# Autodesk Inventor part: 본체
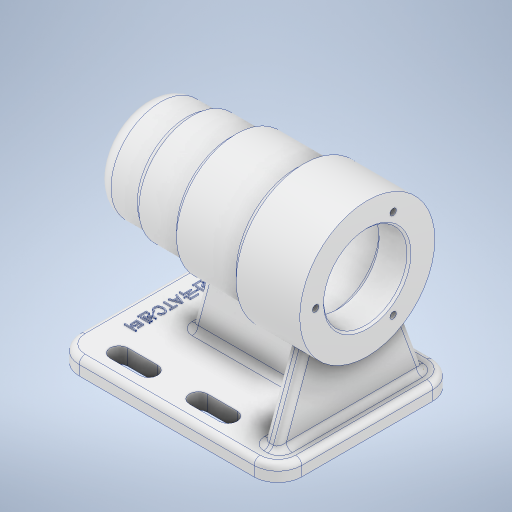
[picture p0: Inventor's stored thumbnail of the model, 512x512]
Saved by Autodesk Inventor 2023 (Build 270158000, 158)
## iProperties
Created: 2022-07
Part Number: 본체
Material: 알루미늄 6061
Document SubType Name: Modeling
Designer: owner
Density: 2.7 g/cm^3
Appearance: 알루미늄 - 평지
Mass: 694.882 g
Surface Area: 704.892 cm^2
Volume: 257.364 cm^3
Author: owner
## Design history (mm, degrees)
sketch "스케치1"
  geometry: L1 (56, -45)-(-56, -45); L2 (-56, -45)-(-56, 45); L3 (-56, 45)-(56, 45); L4 (56, 45)-(56, -45); 1 further point
  constraints: 8 end point, 2 parallel, 1 horizontal, 1 perpendicular
  dimensions: "d0" = 112 distance of L1.start L1.end; "d1" = 90 distance of L3.end L1.start; "d2" = 45 distance from line of point (0, 0) L1; "d3" = 56 distance from line of point (0, 0) L2
extrude "돌출1" new body sketch "스케치1" distance "d4" = 8; taper "d5" = 0 deg
sketch "스케치2"
  geometry: L1 (-36, -33)-(-21, -33); L2 (-36, -37.5)-(-21, -37.5); L3 (-21, -28.5)-(-36, -28.5); L4 (-56, 45)-(-56, -45) reference; L5 (4, -33)-(19, -33); L6 (4, -37.5)-(19, -37.5); L7 (19, -28.5)-(4, -28.5); A1 r 4.5 centre (-36, -33) between (-36, -28.5) and (-36, -37.5); A2 r 4.5 centre (-21, -33) between (-21, -37.5) and (-21, -28.5); A3 r 4.5 centre (4, -33) between (4, -28.5) and (4, -37.5); A4 r 4.5 centre (19, -33) between (19, -37.5) and (19, -28.5); 4 further points
  constraints: 16 end point, 8 point on circle, 8 tangent, 4 centre point, 3 midpoint, 2 horizontal, 2 parallel
  dimensions: "d6" = 15 distance of L1.start L1.end; "d7" = 20 distance from line of L4 L1.start; "d8" = 9 distance from line of L2 point (-28.5, -28.5); "d9" = 33 vertical distance of point (-28.5, -33) point (0, 0); "d10" = 25 distance of L5.start L1.end; "d11" = 15 distance of L5.start L5.end; "d12" = 9 distance between parallel lines of L6 L7; "d13" = 33 distance from line of L5 point (0, 0)
extrude "돌출2" cut sketch "스케치2" distance "d14" = 8; taper "d15" = 0 deg
fillet "모깎기1" dims "d16" = 12
sketch "스케치3"
  geometry: L1 (-56, 70)-(56, 70); L2 (-44, 0)-(44, 0) reference; L3 (-56, 70)-(-56, 87); L4 (-48, 95)-(-32, 95); L5 (-32, 95)-(-32, 97); L6 (-32, 97)-(-10, 97); L7 (-10, 97)-(-10, 100); L8 (-10, 100)-(24, 100); L9 (24, 100)-(24, 104); L10 (24, 104)-(56, 104); L11 (56, 104)-(56, 92); L12 (55, 91)-(41, 91); L13 (41, 91)-(41, 91); L14 (38, 94)-(-10, 94); L15 (-13, 91)-(-13, 91); L16 (-13, 91)-(-24.7, 91); L17 (-25, 90.7)-(-25, 87.5); L18 (-25, 87.5)-(-42.7, 87.5); L19 (-43, 87.2)-(-43, 86); L20 (-43, 86)-(-46.7, 86); L21 (-47, 85.7)-(-47, 80.5); L22 (-47, 80.5)-(-47, 80.5); L23 (-50, 77.5)-(-50, 70); L24 (55, 91)-(56, 92); A1 r 0.3 centre (-46.7, 85.7) between (-46.7, 86) and (-47, 85.7); A2 r 0.3 centre (-42.7, 87.2) between (-42.7, 87.5) and (-43, 87.2); A3 r 0.3 centre (-24.7, 90.7) between (-24.7, 91) and (-25, 90.7); A4 r 8 centre (-48, 87) between (-48, 95) and (-56, 87); A5 r 3 centre (-47, 77.5) between (-47, 80.5) and (-50, 77.5); A6 r 3 centre (-10, 91) between (-10, 94) and (-13, 91); A7 r 3 centre (38, 91) between (41, 91) and (38, 94); 16 further points
  constraints: 46 end point, 18 perpendicular, 17 point on line, 14 point on circle, 14 tangent, 7 centre point, 4 equal radius, 3 midpoint, 2 horizontal, 2 vertical, 2 vertical alignment
  dimensions: "d17" = 112 distance of L1.start L1.end; "d18" = 70 distance between parallel lines of L2 L1; "d19" = 68 diameter of L10 L1; "d20" = 50 diameter of L4 L1; "d21" = 54 diameter of L6 L1; "d22" = 60 diameter of L8 L1; "d23" = 42 diameter of L12 L1; "d24" = 48 diameter of L14 L1; "d25" = 42 diameter of L16 L1; "d26" = 35 diameter of L18 L1; "d27" = 32 diameter of L20 L1; "d28" = 21 diameter of L22 L1; "d29" = 15 distance of point (56, 91) L12.end; "d30" = 54 distance of point (41, 94) point (-13, 94); "d31" = 12 distance of L15.end point (-25, 91); "d32" = 18 distance of L17.end point (-43, 87.5); "d33" = 24 distance of point (-56, 95) L4.end; "d34" = 46 distance from line of point (-10, 98.5) L3; "d35" = 80 distance from line of L3 point (24, 102); "d36" = 3 distance of L21.end point (-50, 80.5); "d37" = 4 distance of L19.end point (-47, 86); "d38" = 0.3 radius of A1; "d39" = 8 radius of A4; "d40" = 3 radius of A5; "d41" = 1 distance of L12.start point (56, 91); "d42" = 1 distance of L11.end point (56, 91) (= d41)
revolve "회전1" sketch "스케치3" stored, may be unused: angle "d43" = 90 deg
fillet "모깎기2" dims "d44" = 3
fillet "모깎기3" dims "d45" = 4
node "작업 평면1"
sketch "스케치4"
  geometry: L1 (66, 8)-(0, 8) reference; L2 (-4, 8)-(11.103, 49.494); L3 (54.897, 49.494)-(70, 8); L4 (-12, 8)-(-12, 0) reference; L5 (78, 0)-(78, 8) reference; L6 (-4, 8)-(70, 8); L7 (66, 8)-(78, 8) reference; A1 r 30 centre (33, 70) between (11.103, 49.494) and (54.897, 49.494); 7 further points
  constraints: 6 end point, 2 point on circle, 2 point on line, 1 centre point, 1 coincident, 1 collinear, 1 midpoint, 5 other
  dimensions: "d47" = 110 deg angle of L1 L2; "d48" = 110 deg angle of L1 L3; "d49" = 8 horizontal distance of point (-12, 4) L2.start; "d50" = 8 distance from line of L5 L3.end
extrude "돌출3" join sketch "스케치4" distance "d51" = 8; taper "d52" = 0 deg
sketch "스케치5"
  geometry: L1 (-44, 8)-(44, 8) reference; L2 (-29, 8)-(-19.27, 44.313); 2 further points
  constraints: 2 end point, 1 point on line
  dimensions: "d53" = 105 deg angle of L1 L2; "d54" = 77 distance of point (48, 8) L2.start; "d55" = 36.31285 vertical distance of L2.start L2.end
feature "리브1" sketch "스케치5" dims "d56" = 1, "d57" = 8, "d58" = 0, "d59" = 0, "d60" = 1, "d61" = 1
fillet "모깎기4" dims "d62" = 3
fillet "모깎기5" dims "d63" = 3
sketch "스케치7"
  geometry: C1 r 34 at (0, 0) reference; 2 further points
  constraints: 1 horizontal alignment
  dimensions: "d72" = 26 distance of C1.centre point (-26, 0)
hole "구멍2" sketch "스케치7" at (-26, 0) diameter "d73" = 3.242; stored, may be unused: countersink angle "d77" = 90 deg, drill point angle "d79" = 118 deg; dims "d74" = 8, "d75" = 4, "d76" = 2, "d78" = 11
sketch "스케치8"
  geometry: L1 (-56, 33)-(-56, -33) reference; 2 further points
  constraints: 1 horizontal alignment, 1 other
  dimensions: "d83" = 12 distance from line of L1 point (-44, 0)
feature "엠보싱1" sketch "스케치8" dims "d1" = 90, "d6" = 15, "d7" = 20, "d8" = 9, "d9" = 33, "d10" = 25, "d11" = 15, "d12" = 9, "d13" = 33, "d84" = 0.5, "d85" = 0
node "솔리드1"
mirror "미러1"
pattern_circular "원형 패턴1" dims angle "d81" = 360 deg
feature "A9D066F2-1C7D-4E18-AEED-F7BC21143FA4" dims "d73" = 3.242, "d74" = 8, "d75" = 4, "d76" = 2, "d77" = 90 deg, "d78" = 11, "d79" = 118 deg
other parameters: "d46" = -8
